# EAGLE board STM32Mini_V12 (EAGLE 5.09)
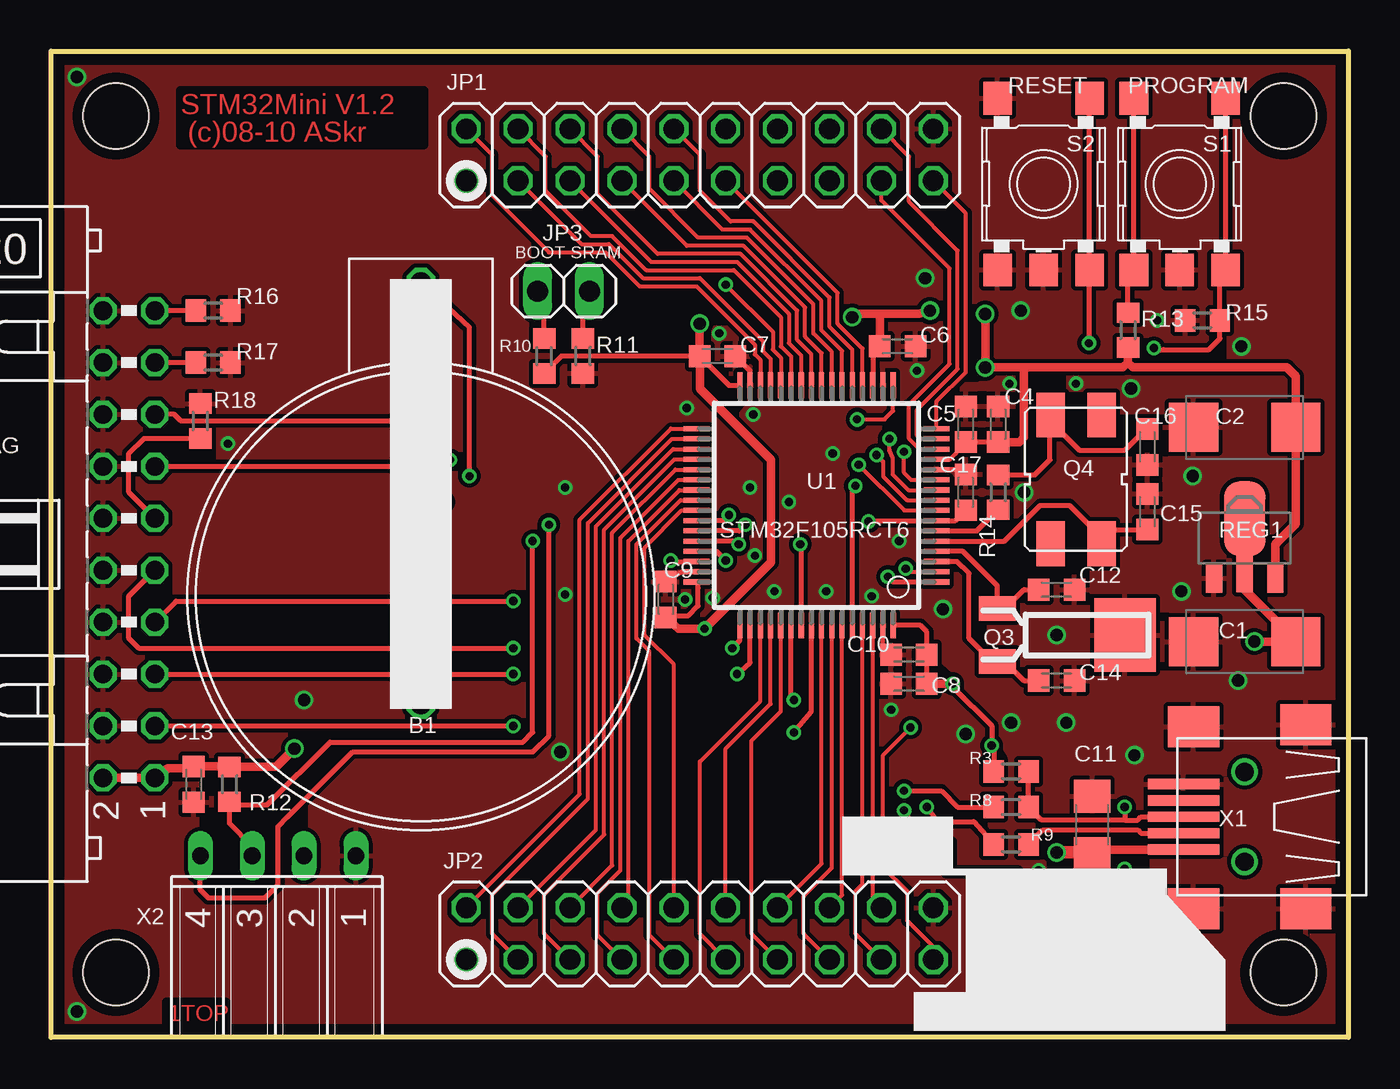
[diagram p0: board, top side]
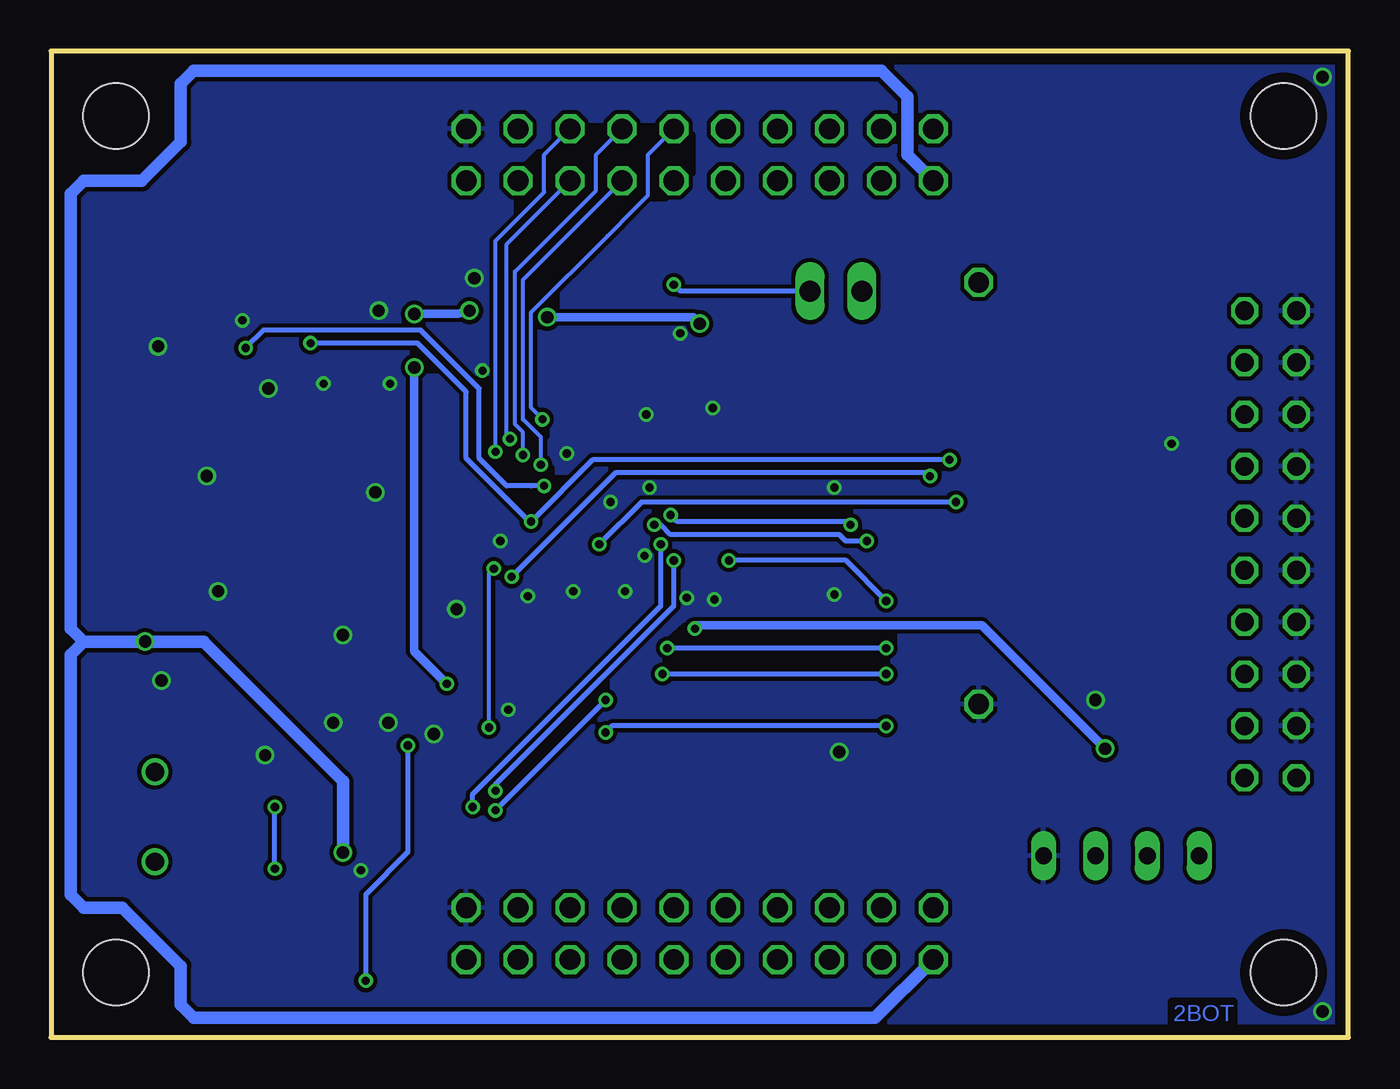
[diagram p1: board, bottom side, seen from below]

Size 63.5 x 48.26 mm. Coordinates in mm from the lower left corner, seen from the top.
Outline: 0,0 0,48.26 63.5,48.26 63.5,0 0,0
Copper layers (1*16): Top 0.035mm / dielectric 1.5mm / Bottom 0.035mm
Design rules "pcb-pool-2009": minimum track width 6mil, minimum drill 12mil, track to track 6mil, track to pad 6mil, pad to pad 6mil, via to via 6mil, smd to smd 6mil, copper to edge 20mil, drill to drill 8mil, minimum pad ring 8mil, minimum via ring 6mil, stop-mask expansion 3mil, vias tented up to drill 0mil, thermal gap 8mil
Holes 3.2 mm at 3.17,3.17 3.17,45.09 60.33,3.17 60.33,45.09
tRestrict: 68 lines
bRestrict: 19 lines

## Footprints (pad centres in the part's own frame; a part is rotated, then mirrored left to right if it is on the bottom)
CR2032-KZH20-1 = drill 1 octagon: + 15.357,0; - -5.283,0
SMC_C = smd 2.4 x 2.4: + -2.5,0; - 2.5,0
C0603K = smd 1.05 x 1.08: 1 -0.875,0; 2 0.875,0
C1206 = smd 1.6 x 1.8: 1 -1.4,0; 2 1.4,0
2X10 = drill 1.016 octagon: 1 -11.43,-1.27; 2 -11.43,1.27; 3 -8.89,-1.27; 4 -8.89,1.27; 5 -6.35,-1.27; 6 -6.35,1.27; 7 -3.81,-1.27; 8 -3.81,1.27; 9 -1.27,-1.27; 10 -1.27,1.27; 11 1.27,-1.27; 12 1.27,1.27; 13 3.81,-1.27; 14 3.81,1.27; 15 6.35,-1.27; 16 6.35,1.27; 17 8.89,-1.27; 18 8.89,1.27; 19 11.43,-1.27; 20 11.43,1.27
1X02 = drill 1.016 long: 1 -1.27,0; 2 1.27,0
SOT23-BEC = smd 1 x 1.4: B -0.95,-1.1; C 0,1.1; E 0.95,-1.1
AKKI_QUARTZ_MS1V-T1K = smd 1.8 x 1.2: 1 2.9,-1.3; 2 2.9,1.3 | smd 3 x 3.6: CASE -3.35,0
AKKI_QUARTZ_MQ = smd 2.2 x 1.4: 1 -3.15,-1.25; 2 3.15,-1.25; 3 3.15,1.25; 4 -3.15,1.25
R0603 = smd 1 x 1.1: 1 -0.85,0; 2 0.85,0
SOT89 = smd 0.8 x 1.4: 1 -1.499,-1.981; 3 1.499,-1.981 | smd 0.8 x 1.9: 2 0,-1.727 | smd 2.032 x 3.65: 2@1 0,0.94
SKHMPXE010 = smd 1.6 x 1.4: 1 -4.2,2.25; 2 4.2,2.25; 3 -4.2,-2.25; 4 4.2,-2.25; 5 4.2,0
STM32_LQFP64 = smd 0.25 x 1.25: 1 -3.75,-5.875; 2 -3.25,-5.875; 3 -2.75,-5.875; 4 -2.25,-5.875; 5 -1.75,-5.875; 6 -1.25,-5.875; 7 -0.75,-5.875; 8 -0.25,-5.875; 9 0.25,-5.875; 10 0.75,-5.875; 11 1.25,-5.875; 12 1.75,-5.875; 13 2.25,-5.875; 14 2.75,-5.875; 15 3.25,-5.875; 16 3.75,-5.875; 33 3.75,5.875; 34 3.25,5.875; 35 2.75,5.875; 36 2.25,5.875; 37 1.75,5.875; 38 1.25,5.875; 39 0.75,5.875; 40 0.25,5.875; 41 -0.25,5.875; 42 -0.75,5.875; 43 -1.25,5.875; 44 -1.75,5.875; 45 -2.25,5.875; 46 -2.75,5.875; 47 -3.25,5.875; 48 -3.75,5.875 | smd 1.25 x 0.25: 17 5.875,-3.75; 18 5.875,-3.25; 19 5.875,-2.75; 20 5.875,-2.25; 21 5.875,-1.75; 22 5.875,-1.25; 23 5.875,-0.75; 24 5.875,-0.25; 25 5.875,0.25; 26 5.875,0.75; 27 5.875,1.25; 28 5.875,1.75; 29 5.875,2.25; 30 5.875,2.75; 31 5.875,3.25; 32 5.875,3.75; 49 -5.875,3.75; 50 -5.875,3.25; 51 -5.875,2.75; 52 -5.875,2.25; 53 -5.875,1.75; 54 -5.875,1.25; 55 -5.875,0.75; 56 -5.875,0.25; 57 -5.875,-0.25; 58 -5.875,-0.75; 59 -5.875,-1.25; 60 -5.875,-1.75; 61 -5.875,-2.25; 62 -5.875,-2.75; 63 -5.875,-3.25; 64 -5.875,-3.75
USB-MB-S = smd 3.5 x 0.5: D+ 3,0; D- 3,0.8; GND 3,-1.6; ID 3,-0.8; VBUS 3,1.6 | smd 2.5 x 2: GND@1 -3,4.5; GND@2 2.5,4.5; GND@3 -3,-4.5; GND@4 2.5,-4.4 | drill 0.9 round: P$5 0,2.2; P$6 0,-2.2
AKKI_FH1X4 = drill 0.813 long: 1 -5.08,0; 2 -2.54,0; 3 0,0; 4 2.54,0
ML20L = drill 0.914 octagon: 1 -11.43,-1.27; 2 -11.43,1.27; 3 -8.89,-1.27; 4 -8.89,1.27; 5 -6.35,-1.27; 6 -6.35,1.27; 7 -3.81,-1.27; 8 -3.81,1.27; 9 -1.27,-1.27; 10 -1.27,1.27; 11 1.27,-1.27; 12 1.27,1.27; 13 3.81,-1.27; 14 3.81,1.27; 15 6.35,-1.27; 16 6.35,1.27; 17 8.89,-1.27; 18 8.89,1.27; 19 11.43,-1.27; 20 11.43,1.27

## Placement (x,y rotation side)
B1  CR2032-KZH20-1  [CR2032-KZH20-1]  18.1,21.59 90 top
C1  15u;16V  [SMC_C]  58.42,19.37 180 top
C2  33u;6V3  [SMC_C]  58.42,29.84 180 top
C3  1n  [C0603K]  55.24,3.02 90 top
C4  22n  [C0603K]  46.35,30 270 top
C5  1u/6V3  [C0603K]  44.77,30 270 top
C6  100n  [C0603K]  41.43,33.81 0 top
C7  100n  [C0603K]  32.62,33.34 180 top
C8  4u7/6V3  [C0603K]  41.99,17.3 180 top
C9  100n  [C0603K]  30.08,21.43 270 top
C10  100n  [C0603K]  41.99,18.73 180 top
C11  100n  [C1206]  50.96,10.4 90 top
C12  8p  [C0603K]  49.21,21.91 0 top
C13  100n  [C0603K]  6.98,12.38 270 top
C14  8p  [C0603K]  49.21,17.46 0 top
C15  22p  [C0603K]  53.66,25.72 270 top
C16  22p  [C0603K]  53.66,28.89 90 top
C17  1n  [C0603K]  44.77,26.67 90 top
JP1  [2X10]  31.75,43.18 0 top
JP2  [2X10]  31.75,5.08 0 top
JP3  [1X02]  25.08,36.51 0 top
Q1  BC817-40  [SOT23-BEC]  52.39,3.02 90 top
Q2  BC817-40  [SOT23-BEC]  46.75,3.73 180 top
Q3  32.768kHz  [AKKI_QUARTZ_MS1V-T1K]  49.21,19.68 180 top
Q4  8MHz  [AKKI_QUARTZ_MQ]  50.16,27.3 270 top
R1  27k  [R0603]  49.37,6.35 90 top
R2  1k5  [R0603]  49.37,3.02 270 top
R3  1k5  [R0603]  46.99,13.02 180 top
R4  470k  [R0603]  51.2,6.35 270 top
R5  470k  [R0603]  42.78,9.05 0 top
R6  1k5  [R0603]  53.02,6.35 270 top
R7  470k  [R0603]  46.75,6.83 0 top
R8  24E  [R0603]  46.99,11.27 0 top
R9  24E  [R0603]  46.99,9.45 0 top
R10  10k  [R0603]  24.13,33.34 270 top
R11  470k  [R0603]  26.03,33.34 90 top
R12  470k  [R0603]  8.73,12.38 90 top
R13  10k  [R0603]  52.7,34.61 270 top
R14  220E  [R0603]  46.35,26.67 90 top
R15  470k  [R0603]  56.36,35.08 0 top
R16  10k  [R0603]  7.94,35.56 180 top
R17  10k  [R0603]  7.94,33.02 180 top
R18  10k  [R0603]  7.3,30.16 270 top
REG1  RH5RA33  [SOT89]  58.42,24.45 0 top
S1  SKHMPSE010  [SKHMPXE010]  55.24,41.75 270 top
S2  SKHMPSE010  [SKHMPXE010]  48.58,41.75 270 top
U1  STM32F105RCT6  [STM32_LQFP64]  37.47,26.04 90 top
X1  AKKI_USB-MB-S  [USB-MB-S]  58.42,10.79 180 top
X2  [AKKI_FH1X4]  9.84,8.89 180 top
X-JTAG  [ML20L]  3.81,24.13 90 top

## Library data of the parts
B1 Q4 REG1 U1 X1 X2 = Akki
C1 C2 = rcl; TYPE: C
C3 C4 C6 C7 C9 C10 C12-C17 R1-R18 = rcl
C5 C8 = rcl; TYPE: cer.
C11 = rcl; SIZE: 1206
JP1-JP3 = pinhead
Q1 Q2 = transistor-npn
Q3 = Akki; MANU: MS1V-T1K
S1 S2 = switch
X-JTAG = con-harting-ml

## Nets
+3V3: C2.+ C4.2 C5.2 C6.1 C7.2 C8.1 C9.2 C10.1 C13.1 Q1.C R3.2 R10.2 R12.2 R13.2 REG1.3 U1.13 U1.19 U1.32 U1.48 U1.64 X-JTAG.1 X-JTAG.2
+5V: C1.+ C11.1 JP1.1 JP2.1 R1.2 REG1.2 X1.VBUS
BOOT0: R15.2 S1.1 S1.2 U1.60
BOOT1: JP3.2 R11.2 U1.28
GND: B1.- C1.- C2.- C3.2 C4.1 C5.1 C6.2 C7.1 C8.2 C9.1 C10.2 C11.2 C12.2 C13.2 C14.2 C15.1 C16.1 C17.2 JP1.20 JP2.20 Q2.E Q3.CASE R4.1 R7.1 R11.1 R15.1 R16.1 R17.1 R18.1 REG1.1 S1.5 S2.3 S2.4 S2.5 U1.12 U1.18 U1.31 U1.47 U1.63 X1.GND X1.GND@1 X1.GND@2 X1.GND@3 X1.GND@4 X2.1 X-JTAG.4 X-JTAG.6 X-JTAG.8 X-JTAG.10 X-JTAG.12 X-JTAG.14 X-JTAG.16 X-JTAG.18 X-JTAG.20
JTAG_DBGACK: R16.2 X-JTAG.19
JTAG_DBGRQ: R17.2 X-JTAG.17
JTAG_RTCK: R18.2 X-JTAG.11
JTAG_TCK: U1.49 X-JTAG.9
JTAG_TDI: U1.50 X-JTAG.5
JTAG_TDO: U1.55 X-JTAG.13
JTAG_TMS: U1.46 X-JTAG.7
JTAG_TRST: U1.56 X-JTAG.3
N$1: R3.1 R6.1 R8.2 X1.D+
N$2: C15.2 Q4.3 U1.5
N$3: R9.2 X1.D-
N$4: Q1.E R6.2
N$5: C3.1 Q1.B R2.2
N$6: Q2.C R1.1 R2.1 R4.2
N$7: JP3.1 R10.1
N$8: R14.1 U1.6
N$9: R13.1 S1.3 S1.4
N$10: B1.+ U1.1
N$11: C16.2 Q4.1 R14.2
N$13: C12.1 Q3.1 U1.4
N$14: C14.1 Q3.2 U1.3
N$16: Q2.B R5.2 R7.2
NRST: C17.1 S2.1 S2.2 U1.7 X-JTAG.15
PA0: JP1.17 U1.14
PA1: JP1.18 U1.15
PA2: JP1.19 U1.16
PA3: JP1.12 U1.17
PA4: JP1.11 U1.20
PA5: JP1.10 U1.21
PA6: JP1.9 U1.22
PA7: JP1.8 U1.23
PA8: JP2.10 U1.41
PB0: JP1.5 U1.26
PB1: JP1.4 U1.27
PB5: JP2.14 U1.57
PB6: JP2.15 U1.58
PB7: JP2.16 U1.59
PB8: JP2.17 U1.61
PB9: JP2.18 U1.62
PB10: JP1.3 U1.29
PB11: JP1.2 U1.30
PB12: JP2.2 U1.33
PB13: JP2.3 U1.34
PB14: JP2.4 U1.35
PB15: JP2.5 U1.36
PC0: JP1.13 U1.8
PC1: JP1.14 U1.9
PC2: JP1.15 U1.10
PC3: JP1.16 U1.11
PC4: JP1.7 U1.24
PC5: JP1.6 U1.25
PC6: JP2.6 U1.37
PC7: JP2.7 U1.38
PC8: JP2.8 U1.39
PC9: JP2.9 U1.40
PC10: JP2.11 U1.51
PC11: JP2.12 U1.52
PC12: JP2.13 U1.53
PC13: JP2.19 U1.2
USART1_RX: R12.1 U1.43 X2.3
USART1_TX: U1.42 X2.4
USB_D+: R8.1 U1.45
USB_D-: R9.1 U1.44
USB_DISCON: R5.1 U1.54

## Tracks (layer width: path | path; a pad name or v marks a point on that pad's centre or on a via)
+3V3  (via drill 0.4, 0.6)
  Top 0.203: U1.13 44,28.29 44.29,28.57 C5.2
  Top 0.254: U1.19 40.22,33.36 C6.1 | C4.2 C5.2 | C10.1 42.86,18.81 42.86,19.84 42.55,20.16 U1.64 | C10.1 C8.1 42.94,17.3 | C10.1 | C7.2 24.98,33.34 R10.2 | R3.2 46.14,14.19 v46.04,14.29 46.04,15.24 44.13,17.14 v44.13,17.3 | C9.2 30.24,20.64 31.19,20.64 31.67,21.11 31.67,21.99 31.67,22.23 U1.48 | Q1.C 48.34,3.02 v48.1,2.78 | 31.75,32.94 32.15,32.94 33.18,31.91 U1.32
  Top 0.406: REG1.3 59.92,24.12 60.92,25.12 C2.+ 60.92,32.35 60.48,32.78 52.94,32.78 52.7,33.02 | 52.7,33.02 R13.2 | 52.7,33.02 52.47,32.78 47.62,32.78 | C4.2 47.38,29.13 47.62,29.37 47.62,32.78 | C8.1 v44.13,17.3 | 47.62,32.78 v45.72,32.78 v45.72,35.4 | v11.91,14.13 11.01,13.23 R12.2 8.71,13.26 C13.1 6.9,13.18 5.71,13.18 5.24,12.7 X-JTAG.1 X-JTAG.2 | v39.21,35.24 39.37,35.4 40.48,35.4 | 40.48,35.4 42.47,35.4 v43.02,35.56 | C6.1 40.56,35.32 40.48,35.4 | C9.2 30.72,20 v31.99,20 35.24,23.26 35.24,28.26 31.75,31.75 31.75,32.94 C7.2 v31.75,34.92
  Bottom 0.254: v46.04,14.29 46.04,9.05 48.1,6.99 v48.1,2.78
  Bottom 0.406: v44.13,17.3 45.72,18.89 v45.72,32.78 | v39.21,35.24 32.07,35.24 v31.75,34.92 | v43.02,35.56 43.58,35.4 v45.72,35.4 | v11.91,14.13 17.94,20.16 31.83,20.16 v31.99,20
+5V  (via drill 0.6)
  Top 0.254: R1.2 49.43,7.2 49.69,7.46 50.32,8.57 C11.1
  Top 0.406: X1.VBUS 51.16,9.2 C11.1 50.91,9.05 | v58.9,19.37 60.48,19.37 | 60.48,19.37 C1.+ | REG1.2 58.42,21.91 60.48,19.84 60.48,19.37
  Top 0.61: v49.21,9.05 50.91,9.05
  Bottom 0.61: v49.21,9.05 49.21,12.54 56.04,19.37 v58.9,19.37 61.91,19.37 | JP1.1 21.59,43.18 21.59,46.04 22.86,47.31 56.52,47.31 57.15,46.67 57.15,43.81 59.05,41.91 61.91,41.91 62.55,41.27 62.55,20 61.91,19.37 | 61.91,19.37 62.55,18.73 62.55,6.99 61.91,6.35 60.01,6.35 57.15,3.49 57.15,1.59 56.52,0.95 23.18,0.95 JP2.1
BOOT0  (via drill 0.4)
  Top 0.254: U1.60 39.22,26.83 v39.37,26.99 | v53.98,33.73 54.29,33.66 54.45,33.66 56.67,33.66 57.21,34.19 R15.2 57.21,36.95 S1.2 S1.1
  Bottom 0.254: v39.37,26.99 40.01,26.99 41.2,26.99 42.55,28.34 42.55,31.75 45.4,34.61 53.1,34.61 v53.98,33.73 | v53.98,33.73
BOOT1  (via drill 0.4)
  Top 0.203: U1.28 35.72,33.26 35.32,33.66 35.32,34.53 v33.02,36.83
  Top 0.254: R11.2 26.04,36.2 JP3.2
  Bottom 0.254: JP3.2 32.7,36.51 v33.02,36.83
GND  (via drill 0.4, 0.6)
  Top 0.203: U1.63 40.72,19.21 C10.2
  Top 0.254: U1.31 34.22,32.62 C7.1 | U1.12 44.53,27.79 C17.2 | U1.47 30.86,22.79 C9.1
  other vias: 42.39,32.62 46.91,31.99 49.21,19.68 47.62,26.67 53.02,13.81 49.69,15.4 46.99,15.4 44.77,14.84 43.66,20.95 40.16,21.59 41.51,24.29 52.86,31.75 47.47,35.56 42.78,37.15 1.27,46.99 1.27,1.27 24.92,13.97 25.16,21.67 25.16,26.91 37.94,21.83 35.4,21.83 32.38,21.51 34.45,23.57 36.12,26.19 34.21,26.91 34.37,30.48 31.11,30.8 54.13,35.08 32.7,34.45 41.12,16.03 58.1,17.46 55.32,21.83 55.88,27.46 58.26,33.81 12.38,16.51 38.26,28.57 48.34,8.18 50.16,31.99 31.04,21.43 8.65,29.05
  pour Top (isolate 0.203): 0.64,47.62 62.87,47.62 62.87,0.64 0.64,0.64
  pour Bottom (isolate 0.203): 0.64,47.62 62.87,47.62 62.87,0.64 0.64,0.64
JTAG_DBGACK
  Top 0.254: R16.2 X-JTAG.19
JTAG_DBGRQ
  Top 0.254: R17.2 X-JTAG.17
JTAG_RTCK
  Top 0.254: X-JTAG.11 3.81,26.67 3.81,28.57 4.55,29.31 R18.2
JTAG_TCK  (via drill 0.4)
  Top 0.254: X-JTAG.9 3.81,21.59 3.81,19.53 4.29,19.05 v22.62,19.05 | 33.4,19.11 v33.34,19.05 33.72,19.43 U1.49
  Bottom 0.254: v22.62,19.05 v33.34,19.05
JTAG_TDI  (via drill 0.4)
  Top 0.254: X-JTAG.5 v22.62,17.78 | U1.50 34.22,18.34 v33.58,17.78
  Bottom 0.254: v22.62,17.78 v33.58,17.78
JTAG_TDO  (via drill 0.4)
  Top 0.254: 36.67,23.97 v36.67,24.13 36.72,24.09 U1.55 | X-JTAG.13 17.46,27.94 v19.21,26.19
  Bottom 0.254: v36.67,24.13 34.61,26.19 v19.21,26.19
JTAG_TMS  (via drill 0.4)
  Top 0.254: U1.46 30.43,23.29 v30.32,23.34 | v22.62,21.35 6.11,21.35 X-JTAG.7
  Bottom 0.254: v30.32,23.34 24.61,23.34 v22.62,21.35
JTAG_TRST  (via drill 0.4)
  Top 0.254: X-JTAG.3 v22.62,15.24 | U1.56 37.22,15.94 v36.35,14.92
  Bottom 0.254: v22.62,15.24 36.04,15.24 v36.35,14.92
N$1  (via drill 0.4)
  Top 0.254: X1.D+ 53.34,10.79 53.18,10.64 52.55,10.64 | 52.55,10.64 48.48,10.64 R8.2 R3.1 | R6.1 53.02,7.94 v52.55,8.26 | v52.55,11.27 52.55,10.64 | R3.1
  Bottom 0.254: v52.55,8.26 v52.55,11.27
N$2
  Top 0.254: U1.5 46.67,24.29 48.42,26.04 49.85,26.04 50.96,24.92 50.96,24.61 Q4.3 52.1,24.84 C15.2
N$3
  Top 0.254: X1.D- 53.35,9.99 53.18,10.16 48.55,10.16 R9.2
N$4
  Top 0.254: R6.2 53.02,4.43 Q1.E
N$5
  Top 0.254: C3.1 55.17,2.07 Q1.B 49.47,2.07 R2.2
N$6
  Top 0.254: R1.1 R2.1 49.24,3.73 46.91,3.73 46.75,3.57 Q2.C | R1.1 | R1.1 R4.2 | R1.1
N$7
  Top 0.254: R10.1 24.13,36.2 JP3.1
N$8
  Top 0.254: U1.6 45.32,24.79 R14.1
N$9
  Top 0.254: S1.3 S1.4 52.7,36.94 R13.1
N$10  (via drill 0.4)
  Top 0.254: U1.1 41.22,22.29 v40.96,22.54 | v20.48,27.46 20.48,34.72 B1.+
  Bottom 0.254: v40.96,22.54 35.88,27.62 20.64,27.62 v20.48,27.46
N$11
  Top 0.254: R14.2 48.16,27.52 48.9,28.26 48.9,30.43 Q4.1 49.37,30 49.37,29.69 50.32,28.73 52.55,28.73 53.58,29.77 C16.2
N$13
  Top 0.254: U1.4 44.64,23.79 46.31,22.11 Q3.1 46.6,21.27 46.99,21.27 47.62,21.91 C12.1
N$14
  Top 0.254: C14.1 47.62,17.46 46.99,18.1 46.6,18.1 Q3.2 45.97,18.73 45.72,18.73 44.93,19.53 44.93,22.7 44.34,23.29 U1.3
N$16
  Top 0.254: Q2.B 47.7,6.73 R7.2 47.6,7.8 47.31,8.1 43.81,8.1 43.66,8.26 43.66,9.03 R5.2
NRST  (via drill 0.4)
  Top 0.254: C17.1 44.26,25.29 U1.7 40.05,25.29 v40.01,25.24 | X-JTAG.15 6.03,30.48 6.35,30.16 17.62,30.16 v19.53,28.26 | v50.8,33.97 50.83,34.16 S2.2 S2.1
  Bottom 0.254: v19.53,28.26 36.99,28.26 v40.01,25.24 | v50.8,33.97 45.56,33.97 43.18,31.59 43.18,28.34 40.08,25.24 v40.01,25.24 | v40.01,25.24 40.16,25.24
PA0
  Top 0.203: U1.14 42.49,28.79 41.99,29.29 41.99,30.96 43.97,32.94 43.97,37.62 40.64,40.96 JP1.17
PA1
  Top 0.203: U1.15 42.55,29.29 42.39,29.45 42.39,30.72 44.37,32.7 44.37,38.5 41.99,40.88 41.99,43.1 JP1.18
PA2
  Top 0.203: JP1.19 44.77,40.32 44.77,32.54 43.34,31.12 U1.16
PA3  (via drill 0.4)
  Top 0.203: U1.17 41.22,30.66 40.8,30.24 v39.45,30.24
  Bottom 0.203: v39.45,30.24 40.01,30.8 40.01,35.48 36.27,39.21 34.92,40.56 34.29,41.2 34.29,43.18 JP1.12
PA4
  Top 0.203: U1.20 39.72,33.71 38.5,34.92 38.5,36.43 34.77,40.16 34.61,40.32 JP1.11
PA5
  Top 0.203: JP1.10 31.75,43.18 31.75,41.43 33.26,39.93 34.37,39.93 38.1,36.2 38.1,34.77 39.22,33.65 U1.21
PA6
  Top 0.203: U1.22 38.72,33.6 37.7,34.61 37.7,36.04 34.21,39.53 32.86,39.53 JP1.9
PA7
  Top 0.203: U1.23 38.22,33.54 37.31,34.45 37.31,35.88 34.05,39.13 31.67,39.13 29.29,41.51 29.29,43.1 JP1.8
PA8
  Top 0.203: JP2.10 30.48,18.26 29.05,19.68 29.05,23.97 30.86,25.79 U1.41
PB0
  Top 0.203: U1.26 36.72,33.37 36.12,33.97 36.12,35.4 33.58,37.94 29.37,37.94 JP1.5
PB1
  Top 0.203: U1.27 36.22,33.32 35.72,33.81 35.72,35.24 33.42,37.54 29.13,37.54 27.46,39.21 26.43,39.21 24.21,41.43 24.21,43.1 JP1.4
PB5
  Top 0.203: U1.57 37.72,8.51 JP2.14
PB6
  Top 0.203: U1.58 38.22,8.29 36.83,6.91 36.83,5.08 JP2.15
PB7
  Top 0.203: U1.59 38.72,6.96 JP2.16
PB8
  Top 0.203: U1.61 39.72,7.49 39.37,7.14 39.37,5.08 JP2.17
PB9
  Top 0.203: U1.62 40.22,6.78 JP2.18
PB10
  Top 0.203: JP1.3 25.96,38.81 27.3,38.81 28.97,37.15 31.75,37.15 34.85,34.05 34.85,33.58 35.22,33.21 U1.29
PB11
  Top 0.203: JP1.2 21.59,43.18 21.59,41.2 24.37,38.42 27.15,38.42 | 27.15,38.42 | 27.15,38.42 28.81,36.75 31.59,36.75 34.37,33.97 34.45,33.89 34.45,33.42 34.72,33.15 U1.30
PB12
  Top 0.203: JP2.2 25.88,11.91 25.88,25.32 30.34,29.79 U1.33
PB13
  Top 0.203: JP2.3 21.59,5.08 21.59,6.99 26.27,11.67 26.27,25.16 30.4,29.29 U1.34
PB14
  Top 0.203: JP2.4 26.67,10.16 26.67,25 30.45,28.79 U1.35
PB15
  Top 0.203: JP2.5 24.13,5.08 24.13,6.99 27.07,9.92 27.07,24.84 30.51,28.29 U1.36
PC0  (via drill 0.4)
  Top 0.203: U1.8 41.76,25.79 v39.53,28.02
  Bottom 0.203: v39.53,28.02 39.53,29.37 40.4,30.24 40.4,37.07 JP1.13
PC1  (via drill 0.4)
  Top 0.203: U1.9 41.9,26.29 40.72,27.46 40.72,28.18 v40.4,28.5
  Bottom 0.203: v40.4,28.5 40.4,29.61 40.8,30 40.8,37.47 36.83,41.43 36.83,43.18 JP1.14
PC2  (via drill 0.4)
  Top 0.203: U1.10 41.95,26.79 41.2,27.54 41.2,28.34 41.04,28.73 v41.04,29.29
  Bottom 0.203: v41.04,29.29 41.2,29.45 41.2,38.81 JP1.15
PC3  (via drill 0.4)
  Top 0.203: U1.11 42.09,27.29 41.75,27.62 v41.75,28.65
  Bottom 0.203: v41.75,28.65 41.75,38.97 39.37,41.35 39.37,43.18 JP1.16
PC4
  Top 0.203: U1.24 37.72,33.48 36.91,34.29 36.91,35.72 33.89,38.73 31.11,38.73 JP1.7
PC5
  Top 0.203: U1.25 37.22,33.43 36.51,34.13 36.51,35.56 33.73,38.34 29.69,38.34 26.75,41.27 26.75,43.1 JP1.6
PC6
  Top 0.203: JP2.6 27.46,8.41 27.46,24.69 30.56,27.79 U1.37
PC7
  Top 0.203: JP2.7 26.75,5 26.75,7.06 27.86,8.18 27.86,24.45 30.7,27.29 U1.38
PC8
  Top 0.203: JP2.8 28.26,6.67 28.26,24.29 30.75,26.79 U1.39
PC9
  Top 0.203: JP2.9 29.29,5 29.29,18.89 28.65,19.53 28.65,24.13 30.81,26.29 U1.40
PC10
  Top 0.203: U1.51 34.72,16.46 31.75,13.49 31.75,5.08 JP2.11
PC11
  Top 0.203: U1.52 35.22,16.32 33.02,14.13 JP2.12
PC12
  Top 0.203: U1.53 35.72,15.95 34.29,14.53 34.29,5.08 JP2.13
PC13  (via drill 0.4)
  Top 0.203: JP2.19 43.18,4.45 41.91,5.71 41.91,7.14 40.72,8.33 40.72,13.81 v42.07,15.16 | v41.83,22.94 41.98,22.79 U1.2
  Bottom 0.203: v42.07,15.16 42.07,22.7 v41.83,22.94
USART1_RX  (via drill 0.4)
  Top 0.254: v23.57,24.29 23.57,14.92 23.1,14.45 13.65,14.45 10.58,11.37 8.89,11.37 R12.1 8.73,10.48 9.84,9.37 X2.3 | U1.43 33.67,24.79 v33.97,25.08
  Bottom 0.254: v23.57,24.29 24.61,24.29 24.92,24.61 33.18,24.61 33.66,25.08 v33.97,25.08
USART1_TX  (via drill 0.4)
  Top 0.254: 11.59,10.79 11.11,10.32 11.11,7.46 10.48,6.83 7.7,6.83 7.3,7.22 X2.4 | 11.59,10.79 | 11.59,10.79 14.76,13.97 23.57,13.97 24.37,14.76 24.37,24.45 24.37,24.61 v24.37,25.08 | U1.42 32.91,25.29 v33.18,25.56
  Bottom 0.254: 24.53,25.08 v24.37,25.08 24.53,25.24 32.86,25.24 v33.18,25.56 | v33.18,25.56
USB_D+  (via drill 0.4)
  Top 0.254: R8.1 44.37,11.27 43.58,12.06 v41.75,12.06 | U1.45 32.57,23.79 v33.02,23.34
  Bottom 0.254: v41.75,12.06 41.75,12.38 41.27,12.86 33.02,21.11 v33.02,23.34
USB_D-  (via drill 0.4)
  Top 0.254: v33.66,24.13 33.5,24.29 U1.44 | R9.1 45.16,10.56 43.42,10.56 v42.86,11.27
  Bottom 0.254: v42.86,11.27 42.86,11.91 41.27,13.49 33.66,21.11 v33.66,24.13
USB_DISCON  (via drill 0.4)
  Top 0.254: R5.1 41.93,10.93 v41.75,11.11 | U1.54 36.22,16.65 v36.35,16.51
  Bottom 0.254: v41.75,11.11 v36.35,16.51

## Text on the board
Top: STM32Mini V1.2 | (c)08-10 ASkr | 1TOP
Bottom: 2BOT
tPlace: RESET | PROGRAM | BOOT SRAM | STM32F105RCT6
